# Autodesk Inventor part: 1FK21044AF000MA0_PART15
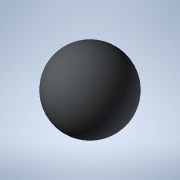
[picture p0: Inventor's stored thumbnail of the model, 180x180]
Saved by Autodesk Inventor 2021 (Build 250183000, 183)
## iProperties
Created: 2025-04
Part Number: 1FK21044AF000MA0_PART15
Material: Generic
Catalog Web Link: www.3dfindit.com
Description: -Servo synchronous motor
Document SubType Name: Modeling
Designer: psAdmin
Mass: 0.137258 g
Surface Area: 1.2868 cm^2
Volume: 0.137258 cm^3
Density: 1 g/cm^3
Appearance: PSOLRGB-212-217-219
Category: PARTsolutions
Title: 1FK21044AF000MA0_PART15
Author: Cadenas PARTsolutions
Comments: Servo synchronous motor
Sending System: PARTsolutions
Preprocessor: ST-DEVELOPER v19.3
PSOL_IDENT_0: {$CADENAS_DATA/23d-libs/siemens_ag/_cat_/39/c4/1fk21044af000ma0.prj},216 {VTYP=3D},{NB=1FK21044AF000
PSOL_IDENT_1: MA0_PART15},{LINA=1FK21044AF000MA0_PART15},{NN=1FK21044AF000MA0_PART15},{NOPRJ=TRUE},{DATE=19.08.202
PSOL_IDENT_2: 5 14:00:33},{GEOMDATE=30.07.2025 02:02:22},{VERSION=},{LINEID=10},{WBVAR=},{WBNUMERIC=}  {NB=1FK2104
PSOL_IDENT_3: 4AF000MA0_PART15},{LINA=1FK21044AF000MA0_PART15},{KT=DUMMY},{PREVIEW=../../../_pool_/cb/72/p_d211_xx
PSOL_IDENT_4: _00434j.png},{DESCSHORT=SIMOTICS S-1FK2 HD, SINAMICS S210 3AC 400V-480V, 1.27 Nm, 3000 rpm},{DESCLON
PSOL_IDENT_5: G=SIMOTICS S-1FK2 HD servo motor M0=1.27 Nm; PN = 0.4 kW at nN=3000 rpm (380-480 V); PN = 0.2 kW at
PSOL_IDENT_6: nN=1500 rpm (200-240 V); degree of protection IP64; cylindrical shaft D19x40mm; absolute encoder 22-
PSOL_IDENT_7: bit + 12-bit multiturn (encoder AM22DQC); with OCC interface; plug size M17, rotatable; SIMOTICS S-1
PSOL_IDENT_8: FK2 servomotorfor a wide range of uses in industrial environments. SIMOTICS S‑1FK2 servomotors are c
PSOL_IDENT_9: ompact synchronous motors with a high dynamic performance that set themselves apart as a result of t
PSOL_IDENT_10: heir high power density, degree of protection and overload capability. The motors are available in t
PSOL_IDENT_11: wo variants: as High Dynamic variant (highest dynamic performance as a result of the low intrinsic m
PSOL_IDENT_12: oment of inertia for applications demanding a high dynamic performance with low moved masses) - and
PSOL_IDENT_13: as Compact variant (precise and stable closed-loop control for medium up to large moved masses as a
PSOL_IDENT_14: result of a medium intrinsic moment of inertia). SIMOTICSS‑1FK2 servomotors fully exploit their stre
PSOL_IDENT_15: ngths in a system with the SINAMICSS210 frequency converter and simple connection using the one cabl
PSOL_IDENT_16: e connection (OCC). Advantages include the short control and positioning times, fast and precise cor
PSOL_IDENT_17: rection of disturbing quantities as well as stable control with a high dynamic performance. The serv
PSOL_IDENT_18: o motors can be configured to address a wide range of requirements. For example with and without hol
PSOL_IDENT_19: ding brake, IP64 or IP65 degree of protection, singleturn or multiturn absolute encoders - to name j
PSOL_IDENT_20: ust a few. Further, the servomotors are available in different shaft heights extending from 20 to 10
PSOL_IDENT_21: 0. A shaft sealing ring is available to achieve an IP65 degree of protection and for subsequent moun
PSOL_IDENT_22: ting at the motor or as spare part. SIMOTICS - the optimum motor for each and every motion control a
PSOL_IDENT_23: pplication.},{INTNO=804766906428},{SUPPLIERALTNO=1FK2104-4AF00-0MA0},{MANUID=1FK21044AF000MA0},{MANU
PSOL_IDENT_24: NAME=Siemens},{MANUTYPEDESC=Synchronous motor 1FK2-HD 1.27 NM},{AAU732=SIMOTICS},{AAO057=S-1FK2},{AA
PSOL_IDENT_25: U734=SIMOTICS S-1FK2 HD servo motor M0=1.27 Nm; PN = 0.4 kW at nN=3000 rpm (380-480 V); PN = 0.2 kW
PSOL_IDENT_26: at nN=1500 rpm (200-240 V); degree of protection IP64; cylindrical shaft D19x40mm; absolute encoder
PSOL_IDENT_27: 22-bit + 12-bit multiturn (encoder AM22DQC); with OCC interface; plug size M17, rotatable;},{AAW338=
PSOL_IDENT_28: Synchronous motor 1FK2-HD 1.27 NM},{AAO742=SIMOTICS},{AAO663=4042948693322},{NOCUPEROU=1},{PRICEQUAN
PSOL_IDENT_29: TITY=1},{QUANTITYMIN=1},{QUANTITYINT=1},{CTN=85015100},{COO=DE},{AAO676=1FK2104-4AF00-0MA0},{AAO677=
PSOL_IDENT_30: Siemens AG},{ORDERUNIT=C62},{CONTENTUNIT=C62}
NB: 1FK21044AF000MA0_PART15
NT: Servo synchronous motor
NBSYN: $MANUID._PART15
LINA: 1FK21044AF000MA0_PART15
CATALOG: SIEMENS
PREVIEW: ../../../_pool_/cb/72/p_d211_xx_00434j.png
DESCSHORT: SIMOTICS S-1FK2 HD, SINAMICS S210 3AC 400V-480V, 1.27 Nm, 3000 rpm
DESCLONG: SIMOTICS S-1FK2 HD servo motor M0=1.27 Nm; PN = 0.4 kW at nN=3000 rpm (380-480 V); PN = 0.2 kW at nN=1500 rpm (200-240 V); degree of protection IP64; cylindrica
INTNO: 804766906428
SUPPLIERALTNO: 1FK2104-4AF00-0MA0
MANUID: 1FK21044AF000MA0
MANUNAME: Siemens
MANUTYPEDESC: Synchronous motor 1FK2-HD 1.27 NM
AAU732: SIMOTICS
AAO057: S-1FK2
AAU734: SIMOTICS S-1FK2 HD servo motor M0=1.27 Nm; PN = 0.4 kW at nN=3000 rpm (380-480 V); PN = 0.2 kW at nN=1500 rpm (200-240 V); degree of protection IP64; cylindrica
AAW338: Synchronous motor 1FK2-HD 1.27 NM
AAO742: SIMOTICS
AAO663: 4042948693322.0
NOCUPEROU: 1
PRICEQUANTITY: 1
QUANTITYMIN: 1
QUANTITYINT: 1
CTN: 85015100
COO: DE
ARTICLENO: 1FK21044AF000MA0_PART15
BOMINFO: 1FK21044AF000MA0_PART15
CREATOR: CADENAS GmbH
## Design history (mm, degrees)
feature "2025_04_17_15_01_28_0038"
body "Solid1"
